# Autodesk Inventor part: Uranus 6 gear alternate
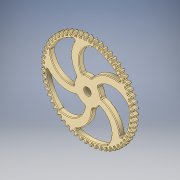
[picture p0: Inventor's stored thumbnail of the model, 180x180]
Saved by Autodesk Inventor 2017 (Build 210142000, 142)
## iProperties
Created: 2016-05
Part Number: Uranus 6 gear alternate
Material: Generic
Document SubType Name: Modeling
Designer: Stan
Density: 1 g/cm^3
Appearance: Beige
Author: Stan
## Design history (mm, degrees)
sketch "Sketch1"
  geometry: A1 r 19.774 centre (24.803, -46.165) between (6.764, -54.264) and (8.832, -57.824); A2 r 19.774 centre (24.803, -46.165) between (6.764, -54.264) and (8.832, -57.824); A3 r 19.774 centre (-14.107, -50.472) between (4.027, -58.356) and (5.266, -54.43); A4 r 19.774 centre (-14.107, -50.472) between (4.027, -58.356) and (5.266, -54.43); A5 r 19.774 centre (29.731, -43.157) between (12.692, -53.19) and (15.139, -56.501); A6 r 19.774 centre (29.731, -43.157) between (12.692, -53.19) and (15.139, -56.501); A7 r 19.774 centre (-8.469, -51.717) between (10.422, -57.558) and (11.222, -53.52); A8 r 19.774 centre (-8.469, -51.717) between (10.422, -57.558) and (11.222, -53.52); A9 r 19.774 centre (34.298, -39.624) between (18.467, -51.471) and (21.263, -54.493); A10 r 19.774 centre (34.298, -39.624) between (18.467, -51.471) and (21.263, -54.493); A11 r 19.774 centre (-2.729, -52.335) between (16.691, -56.063) and (17.041, -51.961); A12 r 19.774 centre (-2.729, -52.335) between (16.691, -56.063) and (17.041, -51.961); A13 r 19.774 centre (38.449, -35.61) between (24.017, -49.127) and (27.129, -51.823); A14 r 19.774 centre (38.449, -35.61) between (24.017, -49.127) and (27.129, -51.823); A15 r 19.774 centre (3.045, -52.318) between (22.757, -53.886) and (22.654, -49.77); A16 r 19.774 centre (3.045, -52.318) between (22.757, -53.886) and (22.654, -49.77); A17 r 19.774 centre (42.133, -31.165) between (29.276, -46.187) and (32.665, -48.524); A18 r 19.774 centre (42.133, -31.165) between (29.276, -46.187) and (32.665, -48.524); A19 r 19.774 centre (8.782, -51.665) between (28.546, -51.056) and (27.992, -46.976); A20 r 19.774 centre (8.782, -51.665) between (28.546, -51.056) and (27.992, -46.976); A21 r 19.774 centre (45.306, -26.34) between (34.179, -42.686) and (37.805, -44.636); A22 r 19.774 centre (45.306, -26.34) between (34.179, -42.686) and (37.805, -44.636); A23 r 19.774 centre (14.412, -50.386) between (33.99, -47.606) and (32.99, -43.612); A24 r 19.774 centre (14.412, -50.386) between (33.99, -47.606) and (32.99, -43.612); A25 r 19.774 centre (47.928, -21.196) between (38.667, -38.667) and (42.486, -40.206); A26 r 19.774 centre (47.928, -21.196) between (38.667, -38.667) and (42.486, -40.206); A27 r 19.774 centre (19.868, -48.494) between (39.02, -43.577) and (37.587, -39.718); A28 r 19.774 centre (19.868, -48.494) between (39.02, -43.577) and (37.587, -39.718); A29 r 19.774 centre (49.969, -15.795) between (42.686, -34.179) and (46.651, -35.289); A30 r 19.774 centre (49.969, -15.795) between (42.686, -34.179) and (46.651, -35.289); A31 r 19.774 centre (25.082, -46.014) between (43.577, -39.02) and (41.728, -35.342); A32 r 19.774 centre (25.082, -46.014) between (43.577, -39.02) and (41.728, -35.342); A33 r 19.774 centre (51.404, -10.202) between (46.187, -29.276) and (50.25, -29.942); A34 r 19.774 centre (51.404, -10.202) between (46.187, -29.276) and (50.25, -29.942); A35 r 19.774 centre (29.992, -42.976) between (47.606, -33.99) and (45.363, -30.537); A36 r 19.774 centre (29.992, -42.976) between (47.606, -33.99) and (45.363, -30.537); A37 r 19.774 centre (52.214, -4.486) between (49.127, -24.017) and (53.239, -24.233); A38 r 19.774 centre (52.214, -4.486) between (49.127, -24.017) and (53.239, -24.233); A39 r 19.774 centre (34.537, -39.416) between (51.056, -28.546) and (48.447, -25.361); A40 r 19.774 centre (34.537, -39.416) between (51.056, -28.546) and (48.447, -25.361); A41 r 19.774 centre (52.391, 1.286) between (51.471, -18.467) and (55.581, -18.229); A42 r 19.774 centre (52.391, 1.286) between (51.471, -18.467) and (55.581, -18.229); A43 r 19.774 centre (38.664, -35.377) between (53.886, -22.757) and (50.943, -19.878); A44 r 19.774 centre (38.664, -35.377) between (53.886, -22.757) and (50.943, -19.878); A45 r 19.774 centre (51.931, 7.041) between (53.19, -12.692) and (57.249, -12.004); A46 r 19.774 centre (51.931, 7.041) between (53.19, -12.692) and (57.249, -12.004); A47 r 19.774 centre (42.321, -30.909) between (56.063, -16.691) and (52.82, -14.153); A48 r 19.774 centre (42.321, -30.909) between (56.063, -16.691) and (52.82, -14.153); A49 r 19.774 centre (50.841, 12.711) between (54.264, -6.764) and (58.222, -5.633); A50 r 19.774 centre (50.841, 12.711) between (54.264, -6.764) and (58.222, -5.633); A51 r 19.774 centre (45.464, -26.066) between (57.558, -10.422) and (54.057, -8.257); A52 r 19.774 centre (45.464, -26.066) between (57.558, -10.422) and (54.057, -8.257); A53 r 19.774 centre (49.135, 18.227) between (54.679, -0.753) and (58.489, 0.806); A54 r 19.774 centre (49.135, 18.227) between (54.679, -0.753) and (58.489, 0.806); A55 r 19.774 centre (48.056, -20.906) between (58.356, -4.027) and (54.637, -2.26); A56 r 19.774 centre (48.056, -20.906) between (58.356, -4.027) and (54.637, -2.26); A57 r 19.774 centre (46.831, 23.522) between (54.43, 5.266) and (58.045, 7.235); A58 r 19.774 centre (46.831, 23.522) between (54.43, 5.266) and (58.045, 7.235); A59 r 19.774 centre (50.064, -15.493) between (58.444, 2.417) and (54.554, 3.764); A60 r 19.774 centre (50.064, -15.493) between (58.444, 2.417) and (54.554, 3.764); A61 r 19.774 centre (43.959, 28.531) between (53.52, 11.222) and (56.897, 13.577); A62 r 19.774 centre (43.959, 28.531) between (53.52, 11.222) and (56.897, 13.577); A63 r 19.774 centre (51.464, -9.891) between (57.824, 8.832) and (53.809, 9.743); A64 r 19.774 centre (51.464, -9.891) between (57.824, 8.832) and (53.809, 9.743)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; 1 further point
  constraints: 912 point on circle, 456 centre point, 8 horizontal alignment, 1360 other
extrude "Extrusion1" new body sketch "Sketch1" distance "d0" = 6.35; taper "d1" = 0 deg
sketch "Sketch2"
  geometry: A1 r 51.942 centre (0, 0) between (43.338, -28.633) and (51.099, 9.321); A2 r 51.942 centre (0, 0) between (40.624, 32.369) and (6.926, 51.479); A3 r 51.942 centre (0, 0) between (-18.231, 48.638) and (-46.819, 22.495); A4 r 51.942 centre (0, 0) between (-51.891, -2.309) and (-35.862, -37.576); A5 r 51.942 centre (0, 0) between (-13.84, -50.065) and (24.655, -45.718); A6 r 32.931 centre (12.286, 30.006) between (-16.296, 46.363) and (-14.27, 10.531); A7 r 24.19 centre (13.278, 28.277) between (6.253, 51.424) and (-7.759, 16.337); A8 r 32.931 centre (-24.741, 20.957) between (-49.13, -1.171) and (-14.425, -10.317); A9 r 24.19 centre (-22.79, 21.367) between (-46.975, 21.838) and (-17.935, -2.331); A10 r 32.931 centre (-27.576, -17.054) between (-14.068, -47.087) and (5.354, -16.907); A11 r 24.19 centre (-27.363, -15.072) between (-35.285, -37.928) and (-3.326, -17.778); A12 r 32.931 centre (7.698, -31.497) between (40.435, -27.93) and (17.734, -0.133); A13 r 24.19 centre (5.879, -30.682) between (25.168, -45.279) and (15.88, -8.656); A14 r 32.931 centre (32.334, -2.412) between (39.058, 29.825) and (5.606, 16.826); A15 r 24.19 centre (30.997, -3.89) between (50.84, 9.944) and (13.14, 12.428); A16 r 16.683 centre (0, 0) between (3.943, 16.21) and (-5.824, 15.633); A17 r 16.683 centre (0, 0) between (16.635, 1.26) and (13.068, 10.37); A18 r 16.683 centre (0, 0) between (6.338, -15.432) and (13.901, -9.224); A19 r 16.683 centre (0, 0) between (-14.199, 8.759) and (-16.668, -0.708); A20 r 16.683 centre (0, 0) between (-12.718, -10.797) and (-4.477, -16.071); A21 r 1.588 centre (-18.254, -0.776) between (-17.935, -2.331) and (-16.668, -0.708); A22 r 1.587 centre (-15.55, 9.592) between (-14.199, 8.759) and (-14.27, 10.531); A23 r 1.587 centre (-17.674, 47.152) between (-16.296, 46.363) and (-18.231, 48.638); A24 r 1.587 centre (-45.388, 21.807) between (-46.819, 22.495) and (-46.975, 21.838); A25 r 1.587 centre (-6.379, 17.121) between (-7.759, 16.337) and (-5.824, 15.633); A26 r 1.588 centre (6.714, 49.905) between (6.926, 51.479) and (6.253, 51.424); A27 r 1.588 centre (39.382, 31.379) between (39.058, 29.825) and (40.624, 32.369); A28 r 1.588 centre (4.318, 17.753) between (3.943, 16.21) and (5.606, 16.826); A29 r 1.588 centre (14.312, 11.357) between (13.14, 12.428) and (13.068, 10.37); A30 r 1.588 centre (49.538, 9.036) between (51.099, 9.321) and (50.84, 9.944); A31 r 1.588 centre (42.013, -27.758) between (40.435, -27.93) and (43.338, -28.633); A32 r 1.588 centre (18.218, 1.379) between (16.635, 1.26) and (17.734, -0.133); A33 r 1.588 centre (15.224, -10.102) between (15.88, -8.656) and (13.901, -9.224); A34 r 1.587 centre (6.942, -16.9) between (6.338, -15.432) and (5.354, -16.907); A35 r 1.588 centre (-13.417, -48.535) between (-14.068, -47.087) and (-13.84, -50.065); A36 r 1.588 centre (23.902, -44.321) between (24.655, -45.718) and (25.168, -45.279); A37 r 1.587 centre (-34.766, -36.428) between (-35.862, -37.576) and (-35.285, -37.928); A38 r 1.587 centre (-50.305, -2.238) between (-49.13, -1.171) and (-51.891, -2.309); A39 r 1.588 centre (-13.928, -11.824) between (-12.718, -10.797) and (-14.425, -10.317); A40 r 1.588 centre (-4.903, -17.6) between (-3.326, -17.778) and (-4.477, -16.071); 2 further points
  constraints: 80 point on circle, 40 centre point, 40 tangent, 19 equal radius, 1 coincident
  dimensions: "d2" = 1.5875 radius of A21
extrude "Extrusion2" cut sketch "Sketch2" distance "d3" = 6.35; taper "d4" = 0 deg
sketch "Sketch3"
  geometry: C1 r 4.763 at (0, 0); 1 further point
  constraints: 1 centre point, 1 coincident
  dimensions: "d5" = 9.525 diameter of C1
extrude "Extrusion3" cut sketch "Sketch3" distance "d6" = 6.35; taper "d7" = 0 deg
fillet "Fillet1" dims "d8" = 0.79375
fillet "Fillet2" dims "d9" = 0.79375
fillet "Fillet3" dims "d10" = 0.79375
fillet "Fillet4" dims "d11" = 0.79375
fillet "Fillet5" dims "d12" = 0.79375
fillet "Fillet6" dims "d13" = 0.79375
fillet "Fillet7" dims "d14" = 0.79375
fillet "Fillet8" dims "d15" = 0.79375
body "Solid1"
